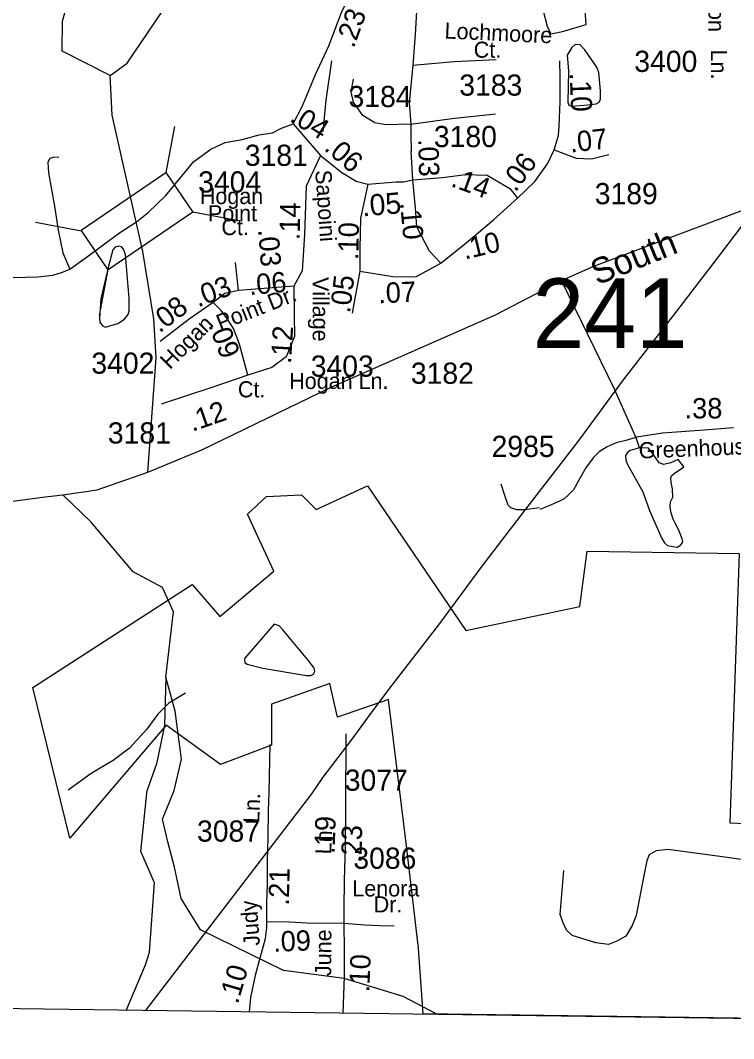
# Model space of a CAD drawing. Extents: x 1547597 to 1699558, y 810033 to 920809.
# Drawn here: x 1618895 to 1623103, y 819952 to 825959 of the extents above; entities that cross this region are included whole.
import ezdxf

# ---------------------------------------------------------------- set-up
doc = ezdxf.new("R2010")
doc.units = 0
for name, color, linetype in [('Exist Boundary Political City Limit New', 7, 'Continuous'), ('Exist Boundary Political CountyLine', 7, 'Continuous'), ('Exist Hydrographic Creek Single Shore', 7, 'Continuous'), ('Exist Hydrographic Creek Single Shore Label', 7, 'Continuous'), ('Exist Hydrographic Misc Water Feature', 7, 'Continuous'), ('Exist Road Non-System Type 51', 7, 'Continuous'), ('Exist Road Secondary Mileage Hundredths English Label', 7, 'Continuous'), ('Exist Road Secondary Structure Standard Bridge CELL', 7, 'Continuous'), ('Exist Road Secondary Structure Standard Bridge Number Label', 7, 'Continuous'), ('Exist Road Secondary Type 51 Attributed', 7, 'Continuous'), ('Exist Road Secondary Type 51 Label', 7, 'Continuous'), ('Exist Road Secondary Type 51 Number Label', 7, 'Continuous'), ('Exist Utilities Electrical Transmission Line', 7, 'Continuous'), ('Map Preparation Boundary City Limit Buffer Line', 7, 'Continuous')]:
    doc.layers.add(name, color=color, linetype=linetype)

msp = doc.modelspace()

# ---------------------------------------------------------------- linework, layer by layer
at = {"layer": 'Exist Boundary Political City Limit New'}
for points in [[(1621271.1, 820096.9), (1621244.1, 820484.8), (1621173.2, 821089.1), (1621067, 821952.3), (1620765.2, 821847.8), (1620721.5, 822046.3), (1620376.6, 821924.3), (1620377.4, 821682.5), (1620075.7, 821569.3), (1619755.7, 821801.5), (1619188.1, 821134.8), (1618969.6, 822023.6), (1619908.4, 822631), (1620073, 822441.5), (1620391.5, 822710.2), (1620235.1, 823046.5), (1620347, 823150.5), (1620554.1, 823159.8), (1620640.6, 823073.7), (1620942.2, 823212.8), (1621523.1, 822359.6), (1622195.8, 822499.9), (1622237.9, 822828.2), (1623135.5, 822813.7), (1623080, 821224.5), (1624219.3, 821176.2)], [(1624188.1, 820058.9), (1623982.5, 820061.2), (1621271.1, 820096.9)]]:
    msp.add_lwpolyline(points, dxfattribs=at)
at = {"layer": 'Exist Boundary Political CountyLine'}
msp.add_lwpolyline([(1606492.6, 820282.1), (1613860.9, 820194.5), (1614148.1, 820194.4), (1614278.7, 820193.7), (1614685.6, 820195), (1614832.4, 820191.9), (1615113.9, 820191.3), (1615321.1, 820189.2), (1615424.8, 820185.5), (1615839, 820171.5), (1623973.3, 820060), (1623995.2, 820060.7), (1624042.9, 820061.2), (1624114.1, 820060.5), (1624171.2, 820059.7), (1624213.4, 820059.1), (1624257.5, 820058.7), (1624364.8, 820057.3), (1624394.8, 820056.9), (1624433.9, 820056.2), (1624457.5, 820055.9), (1624566.7, 820052.4), (1633697.6, 819951.5)], dxfattribs=at)
at = {"layer": 'Exist Hydrographic Creek Single Shore'}
for points in [[(1619424.8, 825632.5), (1619524.7, 825705.9), (1619967.7, 826360), (1620053.8, 826565.1), (1620055.7, 826706.2)], [(1619424.8, 825632.5), (1619142.7, 825776), (1619144.8, 825953.2), (1619179.7, 826083.8)], [(1619647.4, 823293.3), (1619696.5, 823967), (1619681.8, 824198.1), (1619618.7, 824594.5), (1619437.7, 825399.1), (1619424.8, 825632.5)], [(1622087.2, 824423.2), (1622278.3, 824509.2), (1623695.3, 825040.7), (1623925.8, 825167), (1624104.2, 825285.5), (1624233.3, 825311.9), (1624282.5, 825315.4)], [(1619647.4, 823293.3), (1619966.8, 823426), (1620728.3, 823794.9), (1621699, 824221.6), (1622087.2, 824423.2)], [(1622547.5, 823436.4), (1622528.6, 823496.8), (1622400.8, 823783.1), (1622087.2, 824423.2)], [(1619146.2, 823160.5), (1619347.7, 823190), (1619647.4, 823293.3)], [(1616953.7, 823194.7), (1617625.5, 822988.4), (1618367.4, 823057.2), (1619027, 823145), (1619146.2, 823160.5)], [(1619752.9, 822083.2), (1619798.9, 822470.2), (1619733.9, 822612.7), (1619560.7, 822704.9), (1619313.3, 822998.2), (1619146.2, 823160.5)], [(1619802.7, 821414.4), (1619845.7, 821599.4), (1619807.7, 821882.5), (1619752.9, 822083.2)], [(1621352.6, 820095.8), (1621153.8, 820200.7), (1620804.8, 820306.3), (1620446.7, 820352.9), (1619957.7, 820592.7), (1619843.7, 820778.7), (1619804.7, 820963.4), (1619764.7, 821111.9), (1619733.7, 821247.1), (1619802.7, 821414.4)]]:
    msp.add_lwpolyline(points, dxfattribs=at)
at = {"layer": 'Exist Hydrographic Misc Water Feature'}
for points in [[(1621976.6, 826022.5), (1622003.6, 825923.8), (1622024.6, 825878.8), (1622094.2, 825892.9), (1622232, 825935.2), (1622223.6, 826076.8), (1622233.2, 826194.2), (1622229.3, 826215.7), (1622218.5, 826219.2), (1622176.9, 826190.7), (1622143.8, 826181.1), (1622118.1, 826183.9), (1622063.9, 826215.1), (1622049.8, 826214.5), (1622034, 826205.5), (1622002.2, 826168.7), (1621963.2, 826158.3), (1621952.3, 826146.1), (1621952.1, 826131.2), (1621955.9, 826098), (1621976.6, 826022.5)], [(1622296.2, 825682.1), (1622224.1, 825785.5), (1622195.9, 825816.8), (1622166.7, 825814.7), (1622147.8, 825799.4), (1622120.5, 825754.1), (1622129.2, 825661.2), (1622124.8, 825476.4), (1622131, 825458.4), (1622145.6, 825452.5), (1622243.4, 825461.2), (1622292.3, 825467.2), (1622309.4, 825476.8), (1622316.9, 825493), (1622316.7, 825542.6), (1622307.3, 825651), (1622296.2, 825682.1)], [(1619537.9, 824317.3), (1619515, 824578.1), (1619504.8, 824609.6), (1619492.1, 824622.6), (1619474.5, 824626.1), (1619454.4, 824620.7), (1619441.4, 824604.8), (1619414.5, 824508.5), (1619370.6, 824316), (1619361.4, 824199.5), (1619363.6, 824177.8), (1619380.2, 824157.5), (1619397.8, 824148.4), (1619470.4, 824170.9), (1619509.2, 824195.4), (1619530.4, 824222.5), (1619537, 824244.2), (1619537.9, 824317.3)], [(1622547.5, 823436.4), (1622491.5, 823420.3), (1622474.4, 823408.2), (1622465.5, 823391.5), (1622467.2, 823366.1), (1622474.9, 823341.7), (1622567.4, 823177.8), (1622584, 823129.1), (1622606.7, 823067), (1622679.3, 822902.6), (1622694.8, 822877.1), (1622713, 822861.6), (1622743.2, 822855.3), (1622769, 822851.1), (1622788.4, 822863.2), (1622799.4, 822873.8), (1622803.9, 822887.6), (1622796.1, 822910.3), (1622779.5, 822950.2), (1622760.1, 822987.8), (1622745.7, 823015.5), (1622731.9, 823059.8), (1622728.6, 823092.5), (1622731.3, 823118.5), (1622744.1, 823145.1), (1622741.3, 823195), (1622733.5, 823231.5), (1622732.4, 823259.2), (1622736.9, 823271.4), (1622752.4, 823285.2), (1622795, 823314), (1622810, 823325.1), (1622776.2, 823367.2), (1622731.9, 823347.8), (1622690.3, 823338.4), (1622664.3, 823348.9), (1622621.7, 823407.1), (1622600.1, 823434.2), (1622547.5, 823436.4)], [(1620325.3, 822136.1), (1620583.7, 822093.7), (1620609.8, 822094.3), (1620625, 822101.3), (1620633.2, 822118.2), (1620628.1, 822138), (1620600.7, 822174.2), (1620443.3, 822363.4), (1620423, 822386), (1620392.6, 822396.2), (1620217.4, 822193.8), (1620219.9, 822171.3), (1620234.1, 822160.4), (1620325.3, 822136.1)], [(1619752.9, 822083.2), (1619744.8, 821798.8), (1619697.9, 821571.7), (1619643.8, 821416.5)], [(1619519.2, 820116.9), (1619633.3, 820386.1), (1619657.8, 820462.4), (1619686.7, 820870.5), (1619605.7, 821056.1), (1619643.8, 821416.5)]]:
    msp.add_lwpolyline(points, dxfattribs=at)
at = {"layer": 'Exist Road Non-System Type 51'}
msp.add_line((1620362.2, 821402.6), (1620369, 821687.6), dxfattribs=at)
for points in [[(1621233.1, 826010.6), (1621224.5, 825875.9), (1621211.4, 825693.4)], [(1620730.5, 825720.2), (1620697, 825488.7), (1620678.7, 825302.9)], [(1621211.4, 825693.4), (1621189.7, 825471.8), (1621198.4, 825345.8)], [(1621211.4, 825693.4), (1621454.6, 825715.1), (1621702, 825728.2)], [(1621198.4, 825345.8), (1621050.8, 825341.5), (1620985.7, 825354.5), (1620916.2, 825398), (1620859.8, 825476.2), (1620846.7, 825537), (1620859.8, 825610.9)], [(1621198.4, 825345.8), (1621441.5, 825380.6), (1621697.7, 825406.6)], [(1621198.4, 825345.8), (1621197.8, 825282.5), (1621199.8, 825186.5)], [(1619121.5, 825152.5), (1619087.6, 825149), (1619069.5, 825143.3), (1619057.1, 825121.4), (1619062.2, 825059.4), (1619097.2, 824863), (1619119, 824720.7), (1619146.9, 824586.5), (1619187.5, 824490)], [(1621956.1, 823082), (1621871.8, 823070.8), (1621824.2, 823070.9), (1621789.2, 823083.8), (1621773.5, 823098.2), (1621752.3, 823156.4), (1621731.4, 823222.7)], [(1619868.6, 821989.4), (1619771.7, 821930.7), (1619706.8, 821865.8), (1619641.6, 821776.9), (1619540, 821664.5), (1619442.9, 821592), (1619313.9, 821516), (1619176.6, 821417.9)], [(1623262.2, 820991.8), (1623022, 821025.5), (1622714.5, 821067), (1622644.9, 821060.3), (1622604.5, 821035.6), (1622591, 820999.7), (1622573.1, 820914.4), (1622528.2, 820678.7), (1622503.5, 820618.1), (1622467.6, 820555.3), (1622413.7, 820526.1), (1622364.3, 820505.9), (1622290.3, 820517.1), (1622151.1, 820559.8), (1622117.4, 820591.2), (1622097.2, 820633.8), (1622079.3, 820683.2), (1622101.7, 820943.6)], [(1620805.1, 820631.9), (1620926.9, 820622.1), (1621016.9, 820618.7), (1621100.9, 820617.3)]]:
    msp.add_lwpolyline(points, dxfattribs=at)
at = {"layer": 'Exist Road Secondary Structure Standard Bridge CELL'}
for p, q in [((1619804.1, 825332.2), (1619753, 825061)), ((1620183.4, 824776.8), (1619912.2, 824827.9)), ((1619256.6, 824716), (1618985.4, 824767.1)), ((1619412.3, 824488.1), (1619361.2, 824216.9))]:
    msp.add_line(p, q, dxfattribs=at)
msp.add_lwpolyline([(1619912.2, 824827.9), (1619413, 824487), (1619253.8, 824720.2), (1619753, 825061)], close=True, dxfattribs=at)
at = {"layer": 'Exist Road Secondary Type 51 Attributed'}
for p, q in [((1620504.2, 825347.7), (1620665.5, 825161.1)), ((1621209.8, 825018.6), (1621199.8, 825186.5)), ((1620897.2, 824478.5), (1620851.9, 824231.9))]:
    msp.add_line(p, q, dxfattribs=at)
for points in [[(1620504.2, 825347.7), (1620558.1, 825451.3), (1620589.5, 825525.8), (1620636.5, 825639.6), (1620714.9, 825808.2), (1620789.3, 826004.3), (1620887.3, 826212.2), (1620942.2, 826329.9), (1621000.2, 826423.2)], [(1622044.8, 825194.5), (1622068.8, 825278.5), (1622072.7, 825336.4), (1622078.7, 825478.4), (1622080.5, 825626.3), (1622076.9, 825719.6)], [(1618853.4, 824441.2), (1618998.8, 824444.8), (1619087.4, 824455.4), (1619144.2, 824473.2), (1619187.5, 824490), (1619290.8, 824566.1), (1619391, 824639.4), (1619479.7, 824704.9), (1619580, 824770.5), (1619649.4, 824824.5), (1619753.4, 824924.8), (1619919.2, 825125.4), (1620019.5, 825198.7), (1620104.3, 825237.3), (1620204.5, 825256.6), (1620304.8, 825283.6), (1620381.9, 825295.2), (1620435.8, 825322.2), (1620504.2, 825347.7)], [(1620665.5, 825161.1), (1620582.1, 824980), (1620571.1, 824695.3), (1620558, 824480.6), (1620507.7, 824390.8)], [(1620665.5, 825161.1), (1620791, 825060.7), (1620877, 825010.4), (1620945.1, 824992.5)], [(1621827, 824910.6), (1621930.9, 825008.6), (1622004.8, 825112.5), (1622044.8, 825194.5)], [(1622044.8, 825194.5), (1622174.6, 825146.5), (1622264.5, 825142.5), (1622366.4, 825166.5)], [(1621209.8, 825018.6), (1621385.6, 825032.6), (1621522, 825048.6), (1621649.2, 825044.6), (1621783, 824967.2), (1621827, 824910.6)], [(1620945.1, 824992.5), (1620901.6, 824789.5), (1620897.2, 824612.1), (1620897.2, 824478.5)], [(1620945.1, 824992.5), (1621111.9, 825006.6), (1621155.8, 825006.6), (1621209.8, 825018.6)], [(1621376.5, 824526.6), (1621308.5, 824597.5), (1621234.3, 824741.3), (1621225.5, 824850.8), (1621209.8, 825018.6)], [(1621376.5, 824526.6), (1621525.9, 824646.7), (1621572.4, 824684.6), (1621687.2, 824782.7), (1621827, 824910.6)], [(1620181.6, 824364.6), (1620164.1, 824531)], [(1620897.2, 824478.5), (1621092, 824447.8), (1621227.7, 824445.6), (1621376.5, 824526.6)], [(1620181.6, 824364.6), (1620100.6, 824347), (1620032.8, 824294.5)], [(1620507.7, 824390.8), (1620181.6, 824364.6)], [(1620507.7, 824390.8), (1620510, 824219.2), (1620512.2, 824094.3), (1620464.1, 823973.9), (1620378.7, 823910.3), (1620236.5, 823866.5)], [(1620032.8, 824294.5), (1619890.7, 824195.1), (1619720, 824063.7)], [(1620236.5, 823866.5), (1620188.3, 824048.3), (1620153.3, 824140.3), (1620118.1, 824195.9), (1620079.5, 824247.4), (1620032.8, 824294.5)], [(1620236.5, 823866.5), (1620024.2, 823792.1), (1619726.5, 823693.5)], [(1623102.9, 823554.9), (1622929, 823541.1), (1622683.7, 823522.8), (1622530.9, 823500.1), (1622466.6, 823479.5), (1622409, 823466.3), (1622357.5, 823443.6), (1622342, 823433.4), (1622310.4, 823413.1), (1622273.9, 823377.7), (1622230.7, 823319), (1622189.2, 823247), (1622157.6, 823188.9), (1622131.6, 823161.7), (1622102.2, 823135.7), (1622075.6, 823121.9), (1622009.2, 823092), (1621960.5, 823073.1)], [(1620805.1, 820631.9), (1620806.2, 820721.5), (1620807.8, 820880), (1620814.1, 821095.3), (1620815.3, 821317.3), (1620818.1, 821749.8)], [(1620348.8, 820640.3), (1620350, 820751.1), (1620352.4, 820863), (1620353.6, 821002.2), (1620356.3, 821138.2), (1620359.1, 821297.2), (1620362.2, 821402.6)], [(1620248, 820109.5), (1620254.6, 820193.5), (1620284.2, 820333.5), (1620342.1, 820542.9), (1620348.8, 820604.8), (1620348.8, 820640.3)], [(1620805.1, 820631.9), (1620622.4, 820630), (1620482.1, 820638.7), (1620348.8, 820640.3)], [(1620800.1, 820102.2), (1620806.6, 820318.1), (1620808.2, 820471.9), (1620805.1, 820631.9)]]:
    msp.add_lwpolyline(points, dxfattribs=at)
at = {"layer": 'Exist Utilities Electrical Transmission Line'}
msp.add_lwpolyline([(1619633.6, 820115.5), (1620615.1, 821395.4), (1620681.2, 821494.4), (1620852.6, 821717.7), (1620958.6, 821864), (1621075, 822018.1), (1621364.8, 822393.5), (1621626.1, 822747.2), (1621891.2, 823093), (1622184.9, 823474.2), (1622458.6, 823845.7), (1622741.9, 824209.2), (1623027.6, 824580.6), (1623249.9, 824875), (1623443.6, 825123.8), (1623676.2, 825422.1), (1623770.1, 825542.7), (1623929.2, 825748.2), (1624053.5, 825908.1), (1624292.2, 826212.2)], dxfattribs=at)
at = {"layer": 'Map Preparation Boundary City Limit Buffer Line'}
for points in [[(1621271.1, 820096.9), (1621244.1, 820484.8), (1621173.2, 821089.1), (1621067, 821952.3), (1620765.2, 821847.8), (1620721.5, 822046.3), (1620376.6, 821924.3), (1620377.4, 821682.5), (1620075.7, 821569.3), (1619755.7, 821801.5), (1619188.1, 821134.8), (1618969.6, 822023.6), (1619908.4, 822631), (1620073, 822441.5), (1620391.5, 822710.2), (1620235.1, 823046.5), (1620347, 823150.5), (1620554.1, 823159.8), (1620640.6, 823073.7), (1620942.2, 823212.8), (1621523.1, 822359.6), (1622195.8, 822499.9), (1622237.9, 822828.2), (1623135.5, 822813.7), (1623080, 821224.5), (1624219.3, 821176.2)], [(1624188.1, 820058.9), (1623982.5, 820061.2), (1621271.1, 820096.9)]]:
    msp.add_lwpolyline(points, dxfattribs=at)

# ---------------------------------------------------------------- texts
at = {"layer": 'Exist Hydrographic Creek Single Shore Label'}
msp.add_text('South', height=150, rotation=22.00388, dxfattribs=at).set_placement((1622297.8, 824394.7))
at = {"layer": 'Exist Road Secondary Mileage Hundredths English Label'}
for s, height, rotation, p in [('.23', 120, 70.05084, (1620862, 825790.4)), ('.10', 125, 272.20043, (1622135.5, 825649)), ('.04', 120, 328.32822, (1620477.7, 825367.4)), ('.07', 120, 6.51181, (1622141.5, 825178.5)), ('.06', 120, 319.2607, (1620681.5, 825197.6)), ('.03', 120, 271.40557, (1621242, 825258.2)), ('.06', 120, 53.46817, (1621816.1, 824941.2)), ('.14', 120, 340.16477, (1621429.1, 824981.3)), ('.05', 125, 4.83246, (1620914.7, 824801.7)), ('.14', 120, 88.83175, (1620542.8, 824661.2)), ('.10', 120, 275.19641, (1621135.2, 824882.4)), ('.10', 120, 89.11879, (1620889.5, 824544.2)), ('.03', 120, 274.39973, (1620298, 824723.8)), ('.10', 120, 13.18504, (1621517, 824547.2)), ('.03', 120, 20.55244, (1619943.3, 824265.1)), ('.06', 120, 5.19322, (1620247.6, 824337.7)), ('.05', 120, 83.30291, (1620840.2, 824227.8)), ('.07', 120, 2.52528, (1621008.8, 824289.3)), ('.08', 120, 37.33374, (1619716.2, 824111)), ('.09', 120, 291.25457, (1620002.4, 824160.8)), ('.12', 120, 86.49564, (1620491.6, 823930.8)), ('.12', 120, 19.0589, (1619910.2, 823531.4)), ('.38', 120, 0.24592, (1622813.6, 823609.9)), ('.19', 120, 88.47342, (1620749.5, 821040.5)), ('.23', 120, 89.10255, (1620908.1, 820987.2)), ('.21', 120, 88.53392, (1620478.8, 820735.7)), ('.09', 120, 2.35465, (1620388.8, 820463.2)), ('.10', 120, 87.58186, (1620953.3, 820224.3)), ('.10', 120, 73.74781, (1620178.1, 820151.4))]:
    msp.add_text(s, height=height, rotation=rotation, dxfattribs=at).set_placement(p)
at = {"layer": 'Exist Road Secondary Structure Standard Bridge Number Label'}
msp.add_text('241', height=410.1, dxfattribs=at).set_placement((1621916.5, 824026.1))
at = {"layer": 'Exist Road Secondary Type 51 Label'}
for s, rotation, p in [('Creighton', 270, (1622954.4, 826441.3)), ('Lochmoore ', 357.40915, (1621396, 825851.9)), ('Ln.', 270, (1622969.4, 825786.5)), ('Sapoini', 274.08259, (1620634.4, 825073)), ('Village', 270, (1620619.8, 824444.7)), ('Point Dr.', 21.51616, (1620074.6, 824126.8)), ('Hogan ', 45.02051, (1619777.2, 823895.1)), ('Greenhouse', 2.32489, (1622544.8, 823373.3)), ('Ln.', 87.90637, (1620304.3, 821222.7)), ('Ln.', 88.33236, (1620729.3, 821037.7)), ('Judy', 94.35738, (1620309.1, 820502.1)), ('June', 89.75314, (1620729, 820320.4))]:
    msp.add_text(s, height=95, rotation=rotation, dxfattribs=at).set_placement(p)
for s, p in [('Ct. ', (1621569.7, 825738.1)), ('Hogan', (1619953.7, 824874.6)), ('Point', (1620002.1, 824773.3)), ('Ct.', (1620081.3, 824691.7)), ('Ct.', (1620178.7, 823734.6)), ('Hogan Ln.', (1620480.8, 823784)), ('Lenora', (1620853.3, 820790.2)), ('Dr.', (1620979.7, 820696.3))]:
    msp.add_text(s, height=95, dxfattribs=at).set_placement(p)
at = {"layer": 'Exist Road Secondary Type 51 Number Label'}
for s, p in [('3400', (1622516.9, 825654.5)), ('3183', (1621484.5, 825514.4)), ('3184', (1620831.3, 825446.9)), ('3180', (1621334.6, 825211)), ('3181', (1620219.2, 825100.3)), ('3404', (1619944.3, 824943)), ('3189', (1622283.5, 824873.9)), ('3402', (1619314.3, 823874)), ('3403', (1620608.2, 823856.6)), ('3182', (1621198.9, 823814.6)), ('3181', (1619411.6, 823462.2)), ('2985', (1621675, 823383)), ('3077', (1620808.9, 821413.8)), ('3087', (1619937.3, 821113.6)), ('3086', (1620859.6, 820953.5))]:
    msp.add_text(s, height=125, dxfattribs=at).set_placement(p)

doc.saveas('drawing.dxf')
